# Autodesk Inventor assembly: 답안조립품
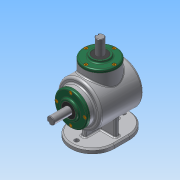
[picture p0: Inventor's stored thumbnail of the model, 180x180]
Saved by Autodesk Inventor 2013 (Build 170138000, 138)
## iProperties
Created: 2016-04
Part Number: 답안조립품
Document SubType Name: Assembly
Designer: Administrator
Author: Administrator
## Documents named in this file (14)
- C:\Users\Administrator\Desktop\460408V1021\답안조립품.iam
- C:\Users\Administrator\Desktop\460408V1021\본체.ipt
- C:\Users\Administrator\Desktop\460408V1021\베어링 6203.ipt
- C:\Users\Administrator\Desktop\460408V1021\커버.ipt
- C:\Users\Administrator\Desktop\460408V1021\M4.ipt
- C:\Users\Administrator\Desktop\460408V1021\오일실 17 32 8.ipt
- C:\Users\Administrator\Desktop\460408V1021\메인 축.ipt
- 메인 축.ipt
- C:\Users\Administrator\Desktop\460408V1021\서브 축.ipt
- 서브 축.ipt
- C:\Users\Administrator\Desktop\460408V1021\키 4x4.ipt
- C:\Users\Administrator\Desktop\460408V1021\키 5x5.ipt
- C:\Users\Administrator\Desktop\460408V1021\메인 베벨기어.ipt
- C:\Users\Administrator\Desktop\460408V1021\서브 베벨기어.ipt
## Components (8 placed, 1 different names)
1. M4:1
2. M4:2
3. M4:3
4. M4:4
5. M4:5
6. M4:6
7. M4:7
8. M4:8
